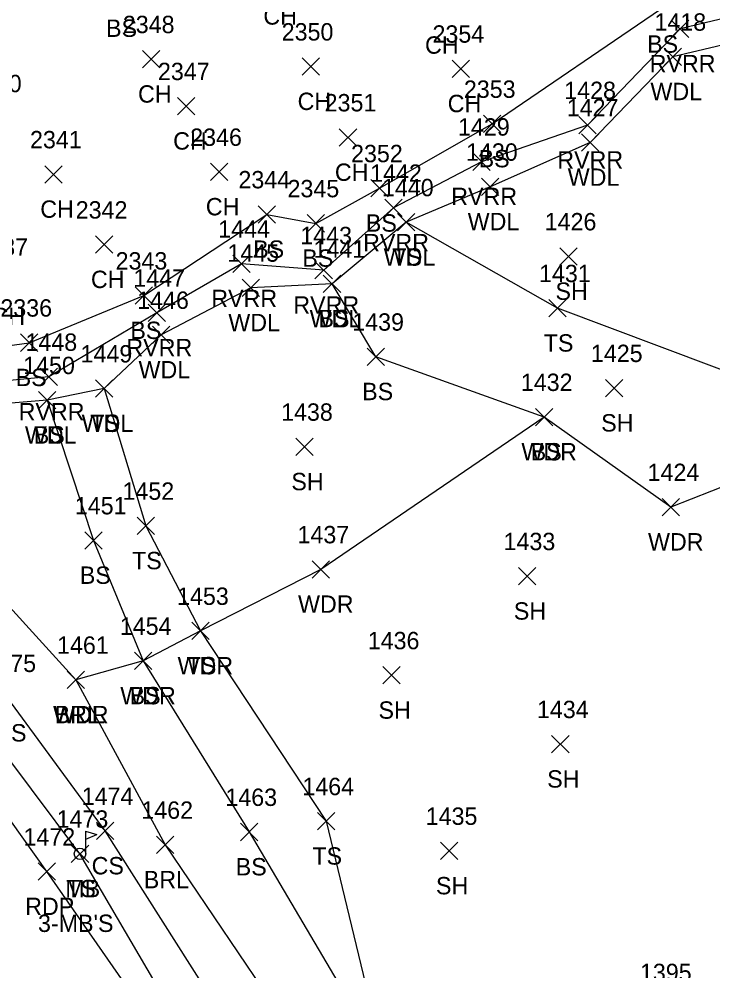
# Model space of a CAD drawing. Extents: x 1501299 to 1502485, y 381423 to 383765.
# Drawn here: x 1501670.4 to 1501750.2, y 383226.1 to 383335.7 of the extents above; entities that cross this region are included whole.
import ezdxf

# ---------------------------------------------------------------- set-up
doc = ezdxf.new("R2010")
doc.units = 0
for name, color, linetype in [('L_A', 7, 'Continuous'), ('L_C', 7, 'Continuous'), ('L_I', 7, 'Continuous'), ('L_TIC', 7, 'Continuous'), ('LABL', 7, 'Continuous'), ('LAWA', 7, 'Continuous'), ('LAWE', 7, 'Continuous'), ('LELB', 7, 'Continuous'), ('LMB', 7, 'Continuous'), ('P_A', 7, 'Continuous'), ('P_I', 7, 'Continuous'), ('P_TIC', 7, 'Continuous'), ('PET', 7, 'Continuous')]:
    doc.layers.add(name, color=color, linetype=linetype)

msp = doc.modelspace()

# ---------------------------------------------------------------- linework, layer by layer
at = {"layer": 'L_TIC'}
for points in [[(1501745.44, 383333.56), (1501747.44, 383335.56)], [(1501747.44, 383333.56), (1501745.44, 383335.56)], [(1501684.59, 383330.06), (1501686.59, 383332.06)], [(1501686.59, 383330.06), (1501684.59, 383332.06)], [(1501744.62, 383330.34), (1501746.62, 383332.34)], [(1501746.62, 383330.34), (1501744.62, 383332.34)], [(1501702.95, 383329.21), (1501704.95, 383331.21)], [(1501704.95, 383329.21), (1501702.95, 383331.21)], [(1501720.22, 383328.96), (1501722.22, 383330.96)], [(1501722.22, 383328.96), (1501720.22, 383330.96)], [(1501688.63, 383324.65), (1501690.63, 383326.65)], [(1501690.63, 383324.65), (1501688.63, 383326.65)], [(1501723.83, 383322.61), (1501725.83, 383324.61)], [(1501725.83, 383322.61), (1501723.83, 383324.61)], [(1501734.81, 383322.47), (1501736.81, 383324.47)], [(1501736.81, 383322.47), (1501734.81, 383324.47)], [(1501707.24, 383321.05), (1501709.24, 383323.05)], [(1501709.24, 383321.05), (1501707.24, 383323.05)], [(1501735.1, 383320.48), (1501737.1, 383322.48)], [(1501737.1, 383320.48), (1501735.1, 383322.48)], [(1501722.6, 383318.26), (1501724.6, 383320.26)], [(1501724.6, 383318.26), (1501722.6, 383320.26)], [(1501673.34, 383316.8), (1501675.34, 383318.8)], [(1501675.34, 383316.8), (1501673.34, 383318.8)], [(1501692.4, 383317.08), (1501694.4, 383319.08)], [(1501694.4, 383317.08), (1501692.4, 383319.08)], [(1501710.85, 383315.2), (1501712.85, 383317.2)], [(1501712.85, 383315.2), (1501710.85, 383317.2)], [(1501723.6, 383315.37), (1501725.6, 383317.37)], [(1501725.6, 383315.37), (1501723.6, 383317.37)], [(1501712.47, 383312.94), (1501714.47, 383314.94)], [(1501714.47, 383312.94), (1501712.47, 383314.94)], [(1501697.89, 383312.19), (1501699.89, 383314.19)], [(1501699.89, 383312.19), (1501697.89, 383314.19)], [(1501703.54, 383311.16), (1501705.54, 383313.16)], [(1501705.54, 383311.16), (1501703.54, 383313.16)], [(1501713.93, 383311.28), (1501715.93, 383313.28)], [(1501715.93, 383311.28), (1501713.93, 383313.28)], [(1501713.93, 383311.28), (1501715.93, 383313.28)], [(1501715.93, 383311.28), (1501713.93, 383313.28)], [(1501679.17, 383308.71), (1501681.17, 383310.71)], [(1501681.17, 383308.71), (1501679.17, 383310.71)], [(1501732.62, 383307.35), (1501734.62, 383309.35)], [(1501734.62, 383307.35), (1501732.62, 383309.35)], [(1501695, 383306.51), (1501697, 383308.51)], [(1501697, 383306.51), (1501695, 383308.51)], [(1501704.44, 383305.76), (1501706.44, 383307.76)], [(1501706.44, 383305.76), (1501704.44, 383307.76)], [(1501696.06, 383303.74), (1501698.06, 383305.74)], [(1501698.06, 383303.74), (1501696.06, 383305.74)], [(1501705.4, 383304.2), (1501707.4, 383306.2)], [(1501707.4, 383304.2), (1501705.4, 383306.2)], [(1501705.4, 383304.2), (1501707.4, 383306.2)], [(1501707.4, 383304.2), (1501705.4, 383306.2)], [(1501683.76, 383302.84), (1501685.76, 383304.84)], [(1501685.76, 383302.84), (1501683.76, 383304.84)], [(1501685.23, 383300.86), (1501687.23, 383302.86)], [(1501687.23, 383300.86), (1501685.23, 383302.86)], [(1501731.35, 383301.39), (1501733.35, 383303.39)], [(1501733.35, 383301.39), (1501731.35, 383303.39)], [(1501685.73, 383298.31), (1501687.73, 383300.31)], [(1501687.73, 383298.31), (1501685.73, 383300.31)], [(1501670.56, 383297.42), (1501672.56, 383299.42)], [(1501672.56, 383297.42), (1501670.56, 383299.42)], [(1501710.43, 383295.8), (1501712.43, 383297.8)], [(1501712.43, 383295.8), (1501710.43, 383297.8)], [(1501672.83, 383293.48), (1501674.83, 383295.48)], [(1501674.83, 383293.48), (1501672.83, 383295.48)], [(1501679.17, 383292.14), (1501681.17, 383294.14)], [(1501681.17, 383292.14), (1501679.17, 383294.14)], [(1501679.17, 383292.14), (1501681.17, 383294.14)], [(1501681.17, 383292.14), (1501679.17, 383294.14)], [(1501737.88, 383292.19), (1501739.88, 383294.19)], [(1501739.88, 383292.19), (1501737.88, 383294.19)], [(1501672.64, 383290.8), (1501674.64, 383292.8)], [(1501674.64, 383290.8), (1501672.64, 383292.8)], [(1501672.64, 383290.8), (1501674.64, 383292.8)], [(1501674.64, 383290.8), (1501672.64, 383292.8)], [(1501729.82, 383288.86), (1501731.82, 383290.86)], [(1501731.82, 383288.86), (1501729.82, 383290.86)], [(1501729.82, 383288.86), (1501731.82, 383290.86)], [(1501731.82, 383288.86), (1501729.82, 383290.86)], [(1501702.23, 383285.43), (1501704.23, 383287.43)], [(1501704.23, 383285.43), (1501702.23, 383287.43)], [(1501744.4, 383278.49), (1501746.4, 383280.49)], [(1501746.4, 383278.49), (1501744.4, 383280.49)], [(1501683.98, 383276.33), (1501685.98, 383278.33)], [(1501685.98, 383276.33), (1501683.98, 383278.33)], [(1501677.94, 383274.65), (1501679.94, 383276.65)], [(1501679.94, 383274.65), (1501677.94, 383276.65)], [(1501704.12, 383271.32), (1501706.12, 383273.32)], [(1501706.12, 383271.32), (1501704.12, 383273.32)], [(1501727.84, 383270.53), (1501729.84, 383272.53)], [(1501729.84, 383270.53), (1501727.84, 383272.53)], [(1501690.26, 383264.23), (1501692.26, 383266.23)], [(1501692.26, 383264.23), (1501690.26, 383266.23)], [(1501690.26, 383264.23), (1501692.26, 383266.23)], [(1501692.26, 383264.23), (1501690.26, 383266.23)], [(1501683.67, 383260.78), (1501685.67, 383262.78)], [(1501685.67, 383260.78), (1501683.67, 383262.78)], [(1501683.67, 383260.78), (1501685.67, 383262.78)], [(1501685.67, 383260.78), (1501683.67, 383262.78)], [(1501712.26, 383259.12), (1501714.26, 383261.12)], [(1501714.26, 383259.12), (1501712.26, 383261.12)], [(1501675.93, 383258.6), (1501677.93, 383260.6)], [(1501677.93, 383258.6), (1501675.93, 383260.6)], [(1501675.93, 383258.6), (1501677.93, 383260.6)], [(1501677.93, 383258.6), (1501675.93, 383260.6)], [(1501675.93, 383258.6), (1501677.93, 383260.6)], [(1501677.93, 383258.6), (1501675.93, 383260.6)], [(1501731.67, 383251.19), (1501733.67, 383253.19)], [(1501733.67, 383251.19), (1501731.67, 383253.19)], [(1501704.73, 383242.32), (1501706.73, 383244.32)], [(1501706.73, 383242.32), (1501704.73, 383244.32)], [(1501679.3, 383241.2), (1501681.3, 383243.2)], [(1501681.3, 383241.2), (1501679.3, 383243.2)], [(1501695.87, 383241.08), (1501697.87, 383243.08)], [(1501697.87, 383241.08), (1501695.87, 383243.08)], [(1501686.2, 383239.6), (1501688.2, 383241.6)], [(1501688.2, 383239.6), (1501686.2, 383241.6)], [(1501676.4, 383238.57), (1501678.4, 383240.57)], [(1501678.4, 383238.57), (1501676.4, 383240.57)], [(1501718.87, 383238.9), (1501720.87, 383240.9)], [(1501720.87, 383238.9), (1501718.87, 383240.9)]]:
    msp.add_lwpolyline(points, dxfattribs=at)
at = {"layer": 'LABL'}
msp.add_lwpolyline([(1501676.93, 383259.6), (1501687.2, 383240.6), (1501706.81, 383211.57)], dxfattribs=at)
at = {"layer": 'LAWA'}
for points in [[(1501779.98, 383346.81), (1501771.13, 383336.51), (1501763.6, 383335.59), (1501745.62, 383331.34), (1501736.1, 383321.48), (1501724.6, 383316.37), (1501714.93, 383312.28), (1501706.4, 383305.2), (1501697.06, 383304.74), (1501686.73, 383299.31), (1501680.17, 383293.14), (1501673.64, 383291.8), (1501663.46, 383290.94), (1501650.48, 383288.16), (1501656.05, 383283.21), (1501664.65, 383273.08), (1501676.93, 383259.6)], [(1501817.85, 383298.93), (1501768.79, 383288.69), (1501745.4, 383279.49), (1501730.82, 383289.86), (1501705.12, 383272.32), (1501691.26, 383265.23), (1501684.67, 383261.78), (1501676.93, 383259.6)]]:
    msp.add_lwpolyline(points, dxfattribs=at)
at = {"layer": 'LAWE'}
msp.add_lwpolyline([(1501778.77, 383348.96), (1501771.99, 383340.49), (1501764.86, 383339), (1501746.44, 383334.56), (1501735.81, 383323.47), (1501723.6, 383319.26), (1501713.47, 383313.94), (1501705.44, 383306.76), (1501696, 383307.51), (1501686.23, 383301.86), (1501673.83, 383294.48), (1501662.64, 383293.46), (1501650.05, 383291.22), (1501647.04, 383295.04)], dxfattribs=at)
at = {"layer": 'LELB'}
for points in [[(1501590.76, 383266.46), (1501598.87, 383270.57), (1501605.03, 383275.32), (1501612.71, 383279.23), (1501613.79, 383281.85), (1501615.91, 383283.69), (1501614.46, 383284.68), (1501622.35, 383292.22), (1501627.42, 383296.44), (1501634.13, 383302.05), (1501643.77, 383300.98), (1501650.03, 383300.07), (1501651.49, 383297.79), (1501662.76, 383297.23), (1501671.56, 383298.42), (1501684.76, 383303.84), (1501698.89, 383313.19), (1501704.54, 383312.16), (1501711.85, 383316.2), (1501724.83, 383323.61), (1501744.21, 383336.81), (1501764.44, 383344.5)], [(1501768.79, 383288.69), (1501732.35, 383302.39), (1501714.93, 383312.28)], [(1501730.82, 383289.86), (1501711.43, 383296.8), (1501706.4, 383305.2)], [(1501740.61, 383142.67), (1501732.68, 383153.53), (1501723.16, 383169.56), (1501715.73, 383180.54), (1501695.36, 383208.82), (1501677.4, 383239.57), (1501666.23, 383254.47), (1501657.2, 383265.28), (1501647.76, 383280.29), (1501635.96, 383296.23)], [(1501736.7, 383153.06), (1501732.68, 383153.53), (1501726.37, 383172.27), (1501718.92, 383183.46), (1501700.04, 383211.1), (1501680.3, 383242.2), (1501669.09, 383257.5), (1501660.99, 383268.48), (1501649.57, 383283.09), (1501640.69, 383295.78)], [(1501680.17, 383293.14), (1501684.98, 383277.33), (1501691.26, 383265.23), (1501705.73, 383243.32), (1501712.37, 383215.8)], [(1501673.64, 383291.8), (1501678.94, 383275.65), (1501684.67, 383261.78), (1501696.87, 383242.08), (1501712.37, 383215.8)]]:
    msp.add_lwpolyline(points, dxfattribs=at)
at = {"layer": 'LMB'}
for p, q in [((1501678.05, 383242.17), (1501679.34, 383241.79)), ((1501678.06, 383239.58), (1501678.06, 383242.17)), ((1501678.06, 383241.27), (1501679.34, 383241.78)), ((1501677.4, 383239.57), (1501677.4, 383239.57))]:
    msp.add_line(p, q, dxfattribs=at)
msp.add_circle((1501677.4, 383239.57), 0.656, dxfattribs=at)
at = {"layer": 'P_TIC'}
for points in [[(1501672.6, 383236.52), (1501674.6, 383238.52)], [(1501674.6, 383236.52), (1501672.6, 383238.52)]]:
    msp.add_lwpolyline(points, dxfattribs=at)
at = {"layer": 'PET'}
msp.add_lwpolyline([(1501787.99, 383066.09), (1501768.48, 383096.75), (1501754.41, 383116.89), (1501736.24, 383144.72), (1501720.75, 383167.97), (1501712.59, 383179.72), (1501694.38, 383207.65), (1501673.6, 383237.52), (1501647.75, 383273.85), (1501633.68, 383294.63), (1501626.39, 383287.88), (1501619.16, 383281.8), (1501626.93, 383271.2), (1501654.42, 383229.17), (1501675.7, 383198.29), (1501696.7, 383166.34)], dxfattribs=at)

# ---------------------------------------------------------------- texts
at = {"layer": 'L_A'}
for s, p in [('CH', (1501698.5, 383335.04)), ('BS', (1501680.4, 383333.63)), ('CH', (1501717.1, 383331.69)), ('BS', (1501742.66, 383331.81)), ('RVRR', (1501742.95, 383329.56)), ('CH', (1501684.08, 383326.06)), ('WDL', (1501743.04, 383326.34)), ('CH', (1501702.44, 383325.21)), ('CH', (1501719.71, 383324.96)), ('CH', (1501688.12, 383320.65)), ('BS', (1501723.27, 383318.61)), ('RVRR', (1501732.32, 383318.47)), ('CH', (1501706.73, 383317.05)), ('WDL', (1501733.52, 383316.48)), ('RVRR', (1501720.12, 383314.26)), ('CH', (1501672.83, 383312.8)), ('CH', (1501691.88, 383313.08)), ('WDL', (1501722.01, 383311.37)), ('BS', (1501710.29, 383311.2)), ('BS', (1501697.33, 383308.19)), ('RVRR', (1501709.98, 383308.94)), ('BS', (1501702.98, 383307.16)), ('WDL', (1501712.34, 383307.28)), ('TS', (1501713.33, 383307.28)), ('CH', (1501678.66, 383304.71)), ('SH', (1501732.11, 383303.35)), ('RVRR', (1501692.51, 383302.51)), ('RVRR', (1501701.95, 383301.76)), ('CH', (1501667.22, 383300.44)), ('WDL', (1501694.47, 383299.74)), ('WDL', (1501703.82, 383300.2)), ('BS', (1501704.84, 383300.2)), ('BS', (1501683.2, 383298.84)), ('TS', (1501730.76, 383297.39)), ('RVRR', (1501682.74, 383296.86)), ('WDL', (1501684.14, 383294.31)), ('BS', (1501670, 383293.42)), ('BS', (1501709.87, 383291.8)), ('RVRR', (1501670.34, 383289.48)), ('WDL', (1501677.59, 383288.14)), ('TS', (1501678.58, 383288.14)), ('SH', (1501737.37, 383288.19)), ('WDL', (1501671.06, 383286.8)), ('BS', (1501672.08, 383286.8)), ('WDR', (1501728.19, 383284.86)), ('BS', (1501729.26, 383284.86)), ('SH', (1501701.72, 383281.43)), ('WDR', (1501742.76, 383274.49)), ('TS', (1501683.39, 383272.33)), ('BS', (1501677.38, 383270.65)), ('WDR', (1501702.49, 383267.32)), ('SH', (1501727.32, 383266.53)), ('WDR', (1501688.63, 383260.23)), ('TS', (1501689.67, 383260.23)), ('WDR', (1501682.04, 383256.78)), ('BS', (1501683.11, 383256.78)), ('WDR', (1501674.3, 383254.6)), ('WDL', (1501674.35, 383254.6)), ('BRL', (1501674.48, 383254.6)), ('SH', (1501711.75, 383255.12)), ('CS', (1501667.53, 383252.5)), ('SH', (1501731.16, 383247.19)), ('TS', (1501704.14, 383238.32)), ('CS', (1501678.74, 383237.2)), ('BS', (1501695.32, 383237.08)), ('TS', (1501675.81, 383234.57)), ('BRL', (1501684.74, 383235.6)), ('SH', (1501718.36, 383234.9)), ('MB', (1501675.71, 383234.57))]:
    msp.add_text(s, height=2, dxfattribs=at).set_placement(p)
at = {"layer": 'L_C'}
msp.add_text("3-MB'S", height=2, dxfattribs=at).set_placement((1501672.57, 383230.57))
at = {"layer": 'L_I'}
for s, p in [('1418', (1501743.5, 383334.34)), ('2348', (1501682.33, 383334.06)), ('2350', (1501700.61, 383333.21)), ('2354', (1501717.96, 383332.96)), ('2347', (1501686.37, 383328.65)), ('2340', (1501664.74, 383327.26)), ('2353', (1501721.57, 383326.61)), ('1428', (1501733.12, 383326.47)), ('2351', (1501705.55, 383325.05)), ('1427', (1501733.41, 383324.48)), ('1429', (1501720.9, 383322.26)), ('2341', (1501671.65, 383320.8)), ('2346', (1501690.08, 383321.08)), ('2352', (1501708.59, 383319.2)), ('1430', (1501721.82, 383319.37)), ('1442', (1501710.78, 383316.94)), ('2344', (1501695.63, 383316.19)), ('2345', (1501701.28, 383315.16)), ('1440', (1501712.15, 383315.28)), ('1440', (1501712.15, 383315.28)), ('2342', (1501676.91, 383312.71)), ('1426', (1501730.87, 383311.35)), ('1444', (1501693.31, 383310.51)), ('1443', (1501702.75, 383309.76)), ('2337', (1501665.48, 383308.44)), ('1441', (1501704.27, 383308.2)), ('1441', (1501704.27, 383308.2)), ('1445', (1501694.36, 383307.74)), ('2343', (1501681.5, 383306.84)), ('1447', (1501683.54, 383304.86)), ('1431', (1501730.22, 383305.39)), ('2336', (1501668.24, 383301.42)), ('1446', (1501683.98, 383302.31)), ('1439', (1501708.73, 383299.8)), ('1448', (1501671.13, 383297.48)), ('1449', (1501677.47, 383296.14)), ('1449', (1501677.47, 383296.14)), ('1425', (1501736.19, 383296.19)), ('1450', (1501670.86, 383294.8)), ('1450', (1501670.86, 383294.8)), ('1432', (1501728.13, 383292.86)), ('1432', (1501728.13, 383292.86)), ('1438', (1501700.54, 383289.43)), ('1424', (1501742.71, 383282.49)), ('1452', (1501682.29, 383280.33)), ('1451', (1501676.81, 383278.65)), ('1437', (1501702.43, 383275.32)), ('1433', (1501726.14, 383274.53)), ('1453', (1501688.57, 383268.23)), ('1453', (1501688.57, 383268.23)), ('1454', (1501681.98, 383264.78)), ('1454', (1501681.98, 383264.78)), ('1436', (1501710.51, 383263.12)), ('1461', (1501674.76, 383262.6)), ('1461', (1501674.76, 383262.6)), ('1461', (1501674.76, 383262.6)), ('1475', (1501666.4, 383260.5)), ('1434', (1501729.98, 383255.19)), ('1464', (1501702.99, 383246.32)), ('1474', (1501677.6, 383245.2)), ('1463', (1501694.13, 383245.08)), ('1462', (1501684.46, 383243.6)), ('1473', (1501674.71, 383242.57)), ('1473', (1501674.71, 383242.57)), ('1435', (1501717.18, 383242.9)), ('1395', (1501741.83, 383224.91))]:
    msp.add_text(s, height=2, dxfattribs=at).set_placement(p)
at = {"layer": 'P_A'}
msp.add_text('RDP', height=2, dxfattribs=at).set_placement((1501671.09, 383232.52))
at = {"layer": 'P_I'}
msp.add_text('1472', height=2, dxfattribs=at).set_placement((1501670.9, 383240.52))

doc.saveas('drawing.dxf')
